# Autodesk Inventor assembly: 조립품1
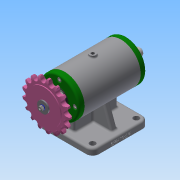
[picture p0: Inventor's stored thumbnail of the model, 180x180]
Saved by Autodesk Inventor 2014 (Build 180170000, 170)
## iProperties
Created: 2019-06
Part Number: 조립품1
Document SubType Name: Assembly
Designer: net
Author: net
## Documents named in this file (11)
- C:\Users\net\Desktop\조립품1.iam
- C:\Users\net\Desktop\490604V1038\부품2.ipt
- C:\Users\net\Desktop\490604V1038\베어링 6203.ipt
- C:\Users\net\Desktop\490604V1038\커버.ipt
- C:\Users\net\Desktop\490604V1038\볼트 M4.ipt
- C:\Users\net\Desktop\490604V1038\스프로킷.ipt
- C:\Users\net\Desktop\490604V1038\스프링와셔.ipt
- C:\Users\net\Desktop\490604V1038\오일 실 17 30 5.ipt
- C:\Users\net\Desktop\490604V1038\축.ipt
- C:\Users\net\Desktop\490604V1038\키 4x4x12.ipt
- C:\Users\net\Desktop\490604V1038\평와셔.ipt
